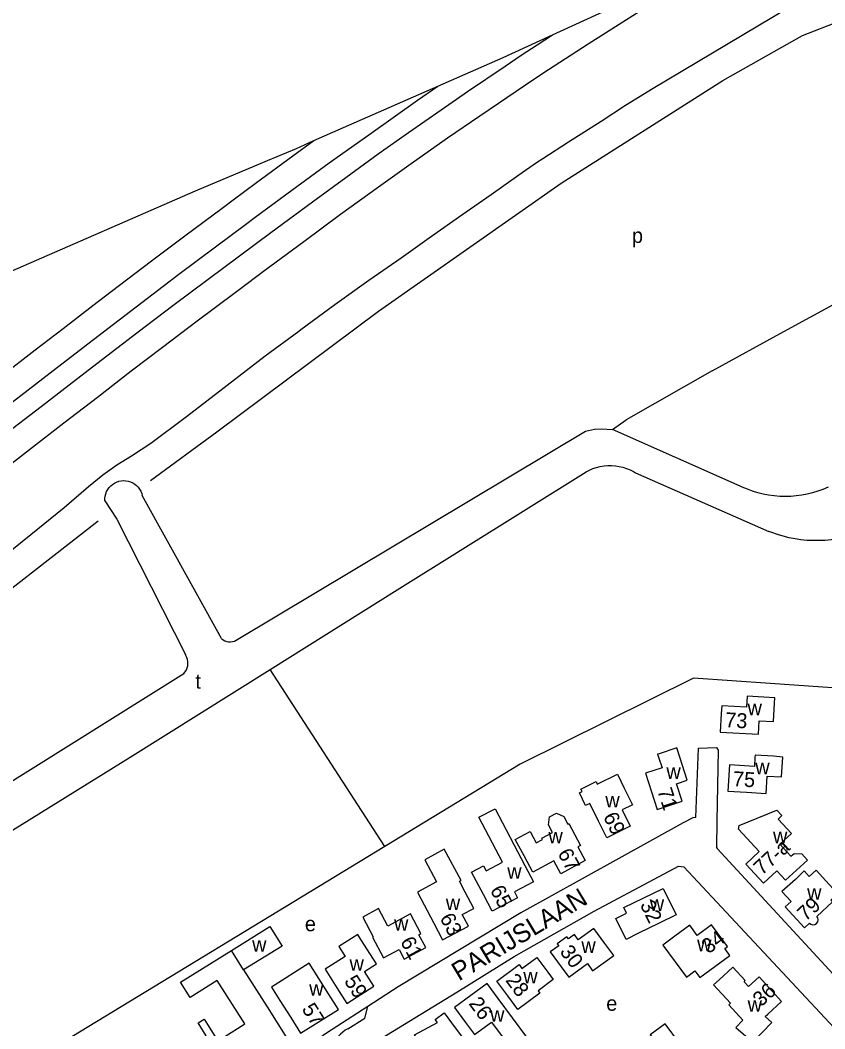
# Model space of a CAD drawing. Extents: x 157768 to 159790, y 387230 to 389604.
# Drawn here: x 158124.1 to 158340.3, y 388926.9 to 389198.2 of the extents above; entities that cross this region are included whole.
import ezdxf

# ---------------------------------------------------------------- set-up
doc = ezdxf.new("R2010")
doc.units = 0
for name, color, linetype in [('BLT_Basislijn', 7, 'Continuous'), ('BLT_Bebouwing', 7, 'Continuous'), ('BLT_Centroide', 7, 'Continuous'), ('BLT_Gemeentegrens', 7, 'Continuous'), ('BLT_Huisnummer', 7, 'Continuous'), ('BLT_Huisnummer_reeks', 7, 'Continuous'), ('BLT_Onderverdeling_panden', 7, 'Continuous'), ('BLT_Straatnaam', 7, 'Continuous'), ('BLT_Vlakafsluiter', 7, 'Continuous')]:
    doc.layers.add(name, color=color, linetype=linetype)

msp = doc.modelspace()

# ---------------------------------------------------------------- linework, layer by layer
at = {"layer": 'BLT_Basislijn'}
for p, q in [((158310.03, 389103.86), (158286.95, 389090.73)), ((158283.27, 389088.07), (158286.95, 389090.73)), ((158317.57, 389072.87), (158283.27, 389088.07)), ((158225.41, 389044.96), (158276.17, 389076.73)), ((158289.42, 389076.46), (158325.33, 389060.71)), ((158178.18, 389031.86), (158156.87, 389070.38)), ((158078.57, 388966.51), (158168.08, 389022.46)), ((158258.46, 388998.06), (158222.07, 388975.94)), ((158222.07, 388975.94), (158126.69, 388917.96))]:
    msp.add_line(p, q, dxfattribs=at)
for points in [[(158159.05, 389074.39), (158176.93, 389087.48), (158220.35, 389119.97), (158269.48, 389154.36), (158312.93, 389181.96), (158334.34, 389194.06), (158344.44, 389198.04), (158364.01, 389204.01), (158376.74, 389206.47), (158394.9, 389208.62), (158440.87, 389212.26), (158481.13, 389217.72), (158514.35, 389223.75), (158530.49, 389227.21)], [(158190.5, 389131.46), (158191.15, 389131.94), (158200.26, 389138.69), (158210.19, 389145.98), (158220.33, 389153.33), (158229.17, 389159.63), (158238.94, 389166.53), (158247.59, 389172.47), (158259.89, 389180.79), (158264.56, 389183.94), (158276.71, 389191.86), (158289.72, 389200.11), (158301.47, 389207.36)], [(158198.94, 389114.58), (158199.46, 389114.97), (158208.62, 389121.75), (158217.76, 389128.23), (158226.48, 389134.26), (158234.61, 389140.07), (158242.81, 389145.8), (158250.68, 389151.33), (158258.08, 389156.57), (158262.88, 389159.87), (158264.5, 389160.99), (158271.41, 389165.43), (158280.2, 389171.05), (158286.77, 389175.33), (158294.17, 389179.91), (158338.26, 389206.26)], [(158187.24, 389137.98), (158191.4, 389141.08), (158202.59, 389149.33), (158211.58, 389155.91), (158220.31, 389162.2), (158228.47, 389168.01), (158237.21, 389174.12), (158244.32, 389179), (158254.39, 389185.85), (158258.75, 389188.74), (158262.98, 389191.55), (158267.1, 389194.25)], [(158184.62, 389143.23), (158187.23, 389145.17), (158197.07, 389152.43), (158207.14, 389159.79), (158218.37, 389167.84), (158230.88, 389176.66), (158236.31, 389180.43)], [(158181.3, 389149.86), (158187.58, 389154.51), (158197.36, 389161.7), (158203.03, 389165.79)], [(158050, 389049.82), (158052.15, 389051.44), (158057.97, 389055.86), (158063.44, 389059.99), (158070.84, 389065.58), (158077.39, 389070.59), (158085.5, 389076.73), (158094.12, 389083.35), (158102.34, 389089.64), (158110.67, 389096.06), (158118.82, 389102.34), (158128.12, 389109.49), (158135.6, 389115.26), (158143.62, 389121.44), (158150.39, 389126.64), (158159.32, 389133.43), (158168.27, 389140.16), (158178.67, 389147.92), (158181.3, 389149.86)], [(158050, 389040.75), (158050.69, 389041.27), (158056.72, 389045.78), (158064.49, 389051.64), (158073.05, 389058.12), (158081.47, 389064.5), (158090.53, 389071.43), (158099.27, 389078.14), (158107.84, 389084.68), (158116, 389090.98), (158124.2, 389097.29), (158132.09, 389103.35), (158141.06, 389110.28), (158149.11, 389116.47), (158158.24, 389123.43), (158166.68, 389129.85), (158176.58, 389137.27), (158184.62, 389143.23)], [(158050, 389033.65), (158051.58, 389034.83), (158057.78, 389039.44), (158065.41, 389045.17), (158071.9, 389050.11), (158079.06, 389055.46), (158085.89, 389060.65), (158092.01, 389065.34), (158099.74, 389071.22), (158106.99, 389076.78), (158114.35, 389082.44), (158120.6, 389087.25), (158129.68, 389094.27), (158137.18, 389100.08), (158145.87, 389106.74), (158155.76, 389114.37), (158165.06, 389121.41), (158174.56, 389128.56), (158183.02, 389134.85), (158187.24, 389137.98)], [(158050, 389024.55), (158050.34, 389024.8), (158056.6, 389029.49), (158062.84, 389034.11), (158069.02, 389038.8), (158076.02, 389044.04), (158084.09, 389050.14), (158092.69, 389056.7), (158101.62, 389063.5), (158110.14, 389070.05), (158118.41, 389076.44), (158126.59, 389082.76), (158135.76, 389089.86), (158144.82, 389096.83), (158153.93, 389103.84), (158162.29, 389110.21), (158171.62, 389117.3), (158181.82, 389124.96), (158190.5, 389131.46)], [(158310.03, 389103.86), (158329.28, 389114.49), (158349.55, 389125.47)], [(158050, 388998.63), (158056.18, 389003.66), (158064.31, 389010.06), (158079.32, 389022.47), (158091.69, 389032.35), (158103.93, 389041.84), (158115.14, 389050.49), (158126.96, 389059.83), (158135.88, 389067.09), (158142.46, 389072.74), (158146.31, 389075.89), (158150.08, 389078.57), (158154.01, 389081.06), (158159.2, 389084.43), (158168.77, 389091.64), (158179.66, 389100.01), (158189.93, 389107.88), (158198.94, 389114.58)], [(158182.55, 389031.69), (158276, 389087.67), (158278.42, 389088.19), (158280.35, 389088.29), (158283.27, 389088.07)], [(158276.17, 389076.73), (158277.08, 389077.2), (158278.02, 389077.59), (158278.99, 389077.91), (158279.99, 389078.15), (158281, 389078.31), (158282.02, 389078.39), (158283.04, 389078.4), (158284.06, 389078.32), (158285.07, 389078.16), (158286.06, 389077.93), (158287.03, 389077.62), (158287.98, 389077.23), (158288.89, 389076.77), (158289.42, 389076.46)], [(158146.83, 389068.91), (158146.83, 389069.54), (158146.9, 389070.18), (158147.06, 389070.79), (158147.29, 389071.39), (158147.59, 389071.95), (158147.96, 389072.47), (158148.39, 389072.94), (158148.88, 389073.35), (158149.41, 389073.7), (158149.99, 389073.97), (158150.59, 389074.17), (158151.22, 389074.3), (158151.85, 389074.35), (158152.49, 389074.31), (158153.12, 389074.2), (158153.73, 389074.01), (158154.31, 389073.74), (158154.85, 389073.41), (158155.34, 389073.01), (158155.79, 389072.55), (158156.17, 389072.04), (158156.48, 389071.48), (158156.72, 389070.89), (158156.87, 389070.38)], [(158341.21, 389072.57), (158339.84, 389071.99), (158338.45, 389071.48), (158337.02, 389071.05), (158335.58, 389070.7), (158334.12, 389070.42), (158332.65, 389070.22), (158331.17, 389070.1), (158329.68, 389070.06), (158328.2, 389070.1), (158326.71, 389070.23), (158325.24, 389070.43), (158323.78, 389070.71), (158322.34, 389071.06), (158320.92, 389071.5), (158319.52, 389072.01), (158318.15, 389072.59), (158317.57, 389072.87)], [(158146.83, 389068.91), (158150.01, 389063.99), (158168.46, 389027.54)], [(157994.33, 388940.13), (158007.4, 388951.69), (158028.48, 388969.75), (158056.52, 388993.48), (158119.76, 389043.78), (158145.02, 389063.56)], [(158349.9, 389060.43), (158348.37, 389059.88), (158346.82, 389059.41), (158345.24, 389059.01), (158343.65, 389058.69), (158342.04, 389058.45), (158340.42, 389058.29), (158338.79, 389058.21), (158337.17, 389058.21), (158335.54, 389058.29), (158333.92, 389058.45), (158332.32, 389058.68), (158330.72, 389059), (158329.14, 389059.4), (158327.59, 389059.87), (158326.05, 389060.42), (158325.33, 389060.71)], [(158191.27, 389023.59), (158225.41, 389044.96)], [(158178.18, 389031.86), (158178.6, 389031.54), (158179.07, 389031.3), (158179.57, 389031.12), (158180.08, 389031.02), (158180.61, 389031), (158181.14, 389031.06), (158181.64, 389031.2), (158182.12, 389031.42), (158182.55, 389031.69)], [(158168.08, 389022.46), (158168.44, 389022.92), (158168.73, 389023.42), (158168.94, 389023.96), (158169.08, 389024.52), (158169.14, 389025.1), (158169.12, 389025.68), (158169.02, 389026.25), (158168.85, 389026.8), (158168.6, 389027.32), (158168.46, 389027.54)], [(158069.05, 388947.54), (158153.58, 389000), (158191.27, 389023.59)], [(158346.25, 389018.32), (158305.03, 389021.22), (158258.46, 388998.06)], [(158305.64, 388983.74), (158306.41, 389002.4), (158311.23, 389002.53), (158311.7, 389001.81), (158311.31, 388982.77)], [(158305.64, 388983.74), (158304.85, 388983.66), (158302.23, 388982.27), (158258.65, 388958.14), (158225.69, 388938.2), (158217.47, 388932.92)], [(158311.31, 388982.77), (158311.19, 388975.67), (158311.4, 388975.41), (158348.99, 388934.64), (158355.99, 388931.76)], [(158217.7, 388922.2), (158241.39, 388936.76), (158256.85, 388946.34), (158278.36, 388958.55), (158301, 388970.67), (158302.4, 388970.48), (158344.06, 388925.81), (158352.55, 388922.18)], [(158217.47, 388932.92), (158206.35, 388925.76), (158186.04, 388911.54), (158162.72, 388894.75), (158159.24, 388895.77), (158145.99, 388887.65)], [(158212.14, 388926.94), (158216.66, 388929.76), (158217.47, 388932.92)], [(158212.14, 388926.94), (158211.44, 388926.52), (158210.78, 388926.04), (158210.17, 388925.49), (158209.62, 388924.89), (158209.13, 388924.24), (158208.71, 388923.54), (158208.36, 388922.8), (158208.08, 388922.04), (158207.88, 388921.24), (158207.76, 388920.44), (158207.71, 388919.62), (158207.75, 388918.81), (158207.87, 388918), (158208.06, 388917.21), (158208.33, 388916.44), (158208.68, 388915.7), (158209.13, 388914.93)]]:
    msp.add_lwpolyline(points, dxfattribs=at)
at = {"layer": 'BLT_Bebouwing'}
for points in [[(158326.85, 389014.53), (158326.94, 389015.96), (158319.5, 389016.4), (158319.32, 389013.4), (158312.62, 389013.8), (158312.5, 389011.72), (158312.2, 389006.73), (158322.47, 389006.12), (158322.69, 389009.77), (158326.55, 389009.54), (158326.85, 389014.53)], [(158301.33, 389000), (158300.52, 389002.46), (158295.77, 389000.91), (158295.4, 389000.8), (158295.66, 389000), (158296.6, 388997.13), (158292.13, 388995.67), (158293.76, 388990.68), (158295.31, 388985.92), (158302.03, 388988.11), (158300.5, 388992.81), (158303.37, 388993.74), (158301.33, 389000)], [(158329.02, 389000), (158326.57, 389000.21), (158321.58, 389000.51), (158321.55, 389000), (158321.39, 388997.48), (158314.69, 388997.88), (158314.27, 388990.83), (158319.26, 388990.53), (158324.57, 388990.21), (158324.85, 388994.9), (158328.7, 388994.67), (158329.02, 389000)], [(158286.44, 388991.62), (158288.64, 388987.13), (158285.88, 388985.78), (158288.04, 388981.39), (158281.72, 388978.29), (158279.51, 388982.78), (158277.2, 388987.51), (158276.05, 388986.95), (158274.36, 388990.39), (158275.11, 388990.75), (158274.79, 388991.4), (158278.85, 388993.4), (158279.17, 388992.75), (158284.58, 388995.4), (158286.44, 388991.62)], [(158259.69, 388970.85), (158262.01, 388966.42), (158256.9, 388963.74), (158257.72, 388962.18), (158250.88, 388958.59), (158248.56, 388963.02), (158245.4, 388969.04), (158248.59, 388970.72), (158249.28, 388969.39), (158253.66, 388971.7), (158247.32, 388983.8), (158251.69, 388986.09), (158259.69, 388970.85)], [(158272.31, 388980.59), (158274.68, 388976.18), (158273.99, 388975.81), (158275.95, 388972.16), (158269.34, 388968.61), (158267.48, 388972.08), (158261.85, 388969.06), (158259.49, 388973.47), (158257.12, 388977.87), (158261.1, 388980), (158262.76, 388976.92), (158264.44, 388977.82), (158264.24, 388978.19), (158267.14, 388979.74), (158266.03, 388981.81), (158266.33, 388983.95), (158268.17, 388984.93), (158270.15, 388984.01), (158271.25, 388981.95), (158271.51, 388982.09), (158272.31, 388980.59)], [(158327.46, 388969.37), (158323.85, 388966.04), (158319.07, 388971.23), (158322.71, 388974.59), (158317.12, 388980.61), (158317.3, 388981.6), (158327.47, 388985.72)], [(158327.47, 388985.72), (158328.8, 388984.28), (158327.77, 388983.33), (158331.38, 388979.44), (158328.26, 388976.54), (158331.24, 388973.32), (158332.06, 388974.08), (158334.17, 388973.96), (158335.69, 388972.31), (158329.77, 388966.88), (158327.46, 388969.37)], [(158243.63, 388963.7), (158242.12, 388966.58), (158242.55, 388966.81), (158238.06, 388975.19), (158232.8, 388972.38), (158235.98, 388966.41), (158230.83, 388963.69), (158235.26, 388955.29), (158237.6, 388950.86), (158244.52, 388954.52), (158242.87, 388957.65), (158245.96, 388959.28), (158243.63, 388963.7)], [(158338.16, 388957.16), (158342.41, 388961.07), (158341.97, 388961.55), (158343.81, 388963.22), (158341.54, 388965.7), (158338, 388969.57), (158336.16, 388967.9), (158334.81, 388969.37), (158332.41, 388967.1), (158328.76, 388963.84), (158331.25, 388961.11), (158329.71, 388959.69), (158334.83, 388954.1), (158336.19, 388955.35), (158336.61, 388955.01), (158337.1, 388954.86), (158337.65, 388954.93), (158338.13, 388955.21), (158338.45, 388955.66), (158338.57, 388956.19), (158338.46, 388956.73), (158338.16, 388957.16)], [(158295.85, 388955.33), (158290.27, 388952.6), (158286.91, 388950.94), (158284.14, 388956.59), (158287.04, 388958.01), (158286.31, 388959.5), (158296.84, 388964.66), (158300.34, 388957.53), (158295.85, 388955.33)], [(158228.95, 388957.79), (158222.91, 388954.51), (158220.34, 388959.24), (158216.12, 388956.94), (158218.98, 388951.68), (158218.72, 388951.53), (158221.74, 388945.98), (158225.88, 388948.24), (158227.31, 388945.61), (158233.1, 388948.76), (158231.22, 388952.22), (158231.79, 388952.53), (158228.95, 388957.79)], [(158180.83, 388947.96), (158191.2, 388954.4), (158194.45, 388949.13), (158184.12, 388942.76)], [(158281.24, 388949.86), (158278.29, 388953.9), (158274.07, 388950.82), (158273.01, 388952.28), (158271.4, 388951.1), (158270.99, 388951.67), (158268.39, 388949.77), (158268.8, 388949.21), (158266.54, 388947.58), (158269.49, 388943.54), (158271.5, 388940.79), (158276.51, 388944.46), (158277.93, 388942.52), (158283.59, 388946.65), (158281.24, 388949.86)], [(158310.78, 388943.7), (158314.8, 388946.67), (158313.46, 388948.48), (158314.18, 388949.01), (158309.88, 388954.83), (158306.06, 388952.01), (158304.04, 388954.76), (158300.01, 388951.79), (158296.82, 388949.43), (158303.19, 388940.81), (158305.43, 388942.46), (158306.73, 388940.71), (158310.78, 388943.7)], [(158215.62, 388950.96), (158214.79, 388952.28), (158209.72, 388949.05), (158211.41, 388946.4), (158206.01, 388942.95), (158209.19, 388937.97), (158211.88, 388933.75), (158219.15, 388938.39), (158216.65, 388942.3), (158219.85, 388944.35), (158215.62, 388950.96)], [(158190.43, 388932.78), (158195.74, 388924.38), (158195.74, 388924.38), (158195.74, 388924.38), (158188.51, 388919.81), (158189.49, 388918.25), (158184.77, 388915.26), (158182.1, 388919.49), (158178.82, 388924.68), (158184.41, 388928.21), (158177.02, 388939.9), (158169.79, 388935.33), (158167.17, 388939.48), (158180.83, 388947.96)], [(158265.87, 388942.1), (158267.32, 388940.14), (158263.29, 388937.15), (158263.75, 388936.52), (158257.83, 388932.13), (158255.15, 388935.74), (158252.17, 388939.76), (158258.15, 388944.2), (158258.92, 388943.17), (158262.89, 388946.11), (158265.87, 388942.1)], [(158184.12, 388942.76), (158190.43, 388932.78)], [(158206.92, 388936.34), (158201.74, 388944.54), (158191.6, 388938.15), (158193.88, 388934.54), (158196.77, 388929.95), (158199.44, 388925.72), (158209.58, 388932.11), (158206.92, 388936.34)], [(158325.04, 388930.87), (158328.72, 388934.25), (158322.66, 388940.88), (158319.8, 388938.27), (158318.62, 388939.56), (158318.96, 388939.86), (158315.64, 388943.49), (158311.96, 388940.11), (158310.44, 388938.72), (158314.96, 388933.78), (158314.52, 388933.38), (158318.3, 388929.25), (158316.42, 388927.26), (158320.96, 388923.28), (158326.06, 388928.65), (158324.3, 388930.2), (158325.04, 388930.87)], [(158252.52, 388935.09), (158249.54, 388939.1), (158240.78, 388932.6), (158243.76, 388928.58), (158246.15, 388925.36), (158250.7, 388928.74), (158257.56, 388919.51), (158253.77, 388916.7), (158251.38, 388919.93), (158248.17, 388917.55), (158252.94, 388911.12), (158264.12, 388919.44), (158252.52, 388935.09)], [(158241.02, 388927.19), (158246.94, 388919.21), (158241.34, 388916.37), (158242, 388915.49), (158238.96, 388913.23), (158232.99, 388921.27), (158230.01, 388925.29), (158236.19, 388928.65), (158235.63, 388929.41), (158238.05, 388931.2), (158241.02, 388927.19)], [(158301.3, 388923.07), (158297.44, 388928.29), (158293.4, 388925.3), (158295.32, 388922.71), (158289.69, 388918.55), (158295.02, 388911.34), (158302.06, 388916.54), (158301.64, 388917.11), (158304.27, 388919.05), (158301.3, 388923.07)]]:
    msp.add_lwpolyline(points, dxfattribs=at)
msp.add_lwpolyline([(158173.49, 388929.47), (158179.47, 388919.93), (158176.84, 388918.27), (158178.59, 388915.49), (158174.79, 388913.11), (158175.86, 388911.41), (158171.3, 388908.55), (158167.46, 388914.66), (158167.05, 388914.41), (158164.38, 388918.66), (158167.34, 388920.52), (158167.19, 388920.74), (158174.05, 388925.04), (158171.9, 388928.48)], close=True, dxfattribs=at)
at = {"layer": 'BLT_Gemeentegrens'}
for p, q in [((158253.9, 389188.18), (158267.1, 389194.25)), ((158236.31, 389180.43), (158253.9, 389188.18)), ((158203.03, 389165.79), (158236.31, 389180.43))]:
    msp.add_line(p, q, dxfattribs=at)
for points in [[(158267.1, 389194.25), (158315.34, 389216.44), (158320.42, 389218.72)], [(158190.56, 389160.43), (158198.3, 389163.7), (158203.03, 389165.79)], [(158121.43, 389130.57), (158171.17, 389152.25), (158190.56, 389160.43)]]:
    msp.add_lwpolyline(points, dxfattribs=at)
at = {"layer": 'BLT_Onderverdeling_panden'}
msp.add_line((158184.12, 388942.76), (158180.83, 388947.96), dxfattribs=at)
at = {"layer": 'BLT_Vlakafsluiter'}
msp.add_line((158222.07, 388975.94), (158191.27, 389023.59), dxfattribs=at)

# ---------------------------------------------------------------- texts
at = {"layer": 'BLT_Centroide'}
for s, p in [('p', (158288.49, 389138.28)), ('t', (158171.14, 389018.4)), ('w', (158319.56, 389011.25)), ('w', (158297.75, 388994.14)), ('w', (158321.64, 388995.38)), ('w', (158281.34, 388986.44)), ('w', (158266.04, 388976.78)), ('w', (158326.41, 388976.84)), ('w', (158254.97, 388967.27)), ('w', (158335.58, 388961.62)), ('w', (158238.47, 388958.86)), ('w', (158293.27, 388958.62)), ('w', (158224.55, 388953.31)), ('e', (158200.58, 388953.15)), ('w', (158186.4, 388947.66)), ('w', (158274.89, 388947.34)), ('w', (158306.02, 388947.78)), ('w', (158212.58, 388942.53)), ('w', (158259.29, 388939.12)), ('w', (158201.73, 388935.84)), ('e', (158281.59, 388931.76)), ('w', (158250.37, 388928.84)), ('w', (158319.58, 388931.5))]:
    msp.add_text(s, height=4, dxfattribs=at).set_placement(p)
at = {"layer": 'BLT_Huisnummer'}
for s, rotation, p in [('73', 356.5734, (158313.46, 389008.06)), ('75', 356.5723, (158315.55, 388992.21)), ('71', 288.0581, (158295.26, 388990.99)), ('69', 296.1397, (158280.67, 388984)), ('67', 298.2356, (158268.42, 388974.11)), ('65', 297.6668, (158250.26, 388964.24)), ('79', 42.8687, (158335.18, 388955.64)), ('32', 296.0941, (158290.57, 388960.3)), ('63', 297.8103, (158236.74, 388956.74)), ('61', 298.5483, (158226.1, 388950.38)), ('34', 36.4436, (158309.09, 388946.93)), ('30', 306.6594, (158268.93, 388947.62)), ('59', 302.5362, (158211.01, 388939.74)), ('28', 306.6594, (158254.36, 388939.91)), ('36', 42.4626, (158323.2, 388932.65)), ('26', 306.6594, (158244.46, 388933.68)), ('57', 302.2216, (158199.62, 388932.26))]:
    msp.add_text(s, height=4, rotation=rotation, dxfattribs=at).set_placement(p)
at = {"layer": 'BLT_Huisnummer_reeks'}
msp.add_text('77-a', height=4, rotation=42.8687, dxfattribs=at).set_placement((158323.46, 388968.01))
at = {"layer": 'BLT_Straatnaam'}
msp.add_text('PARIJSLAAN', height=5, rotation=31.0376, dxfattribs=at).set_placement((158241.97, 388939.65))

doc.saveas('drawing.dxf')
